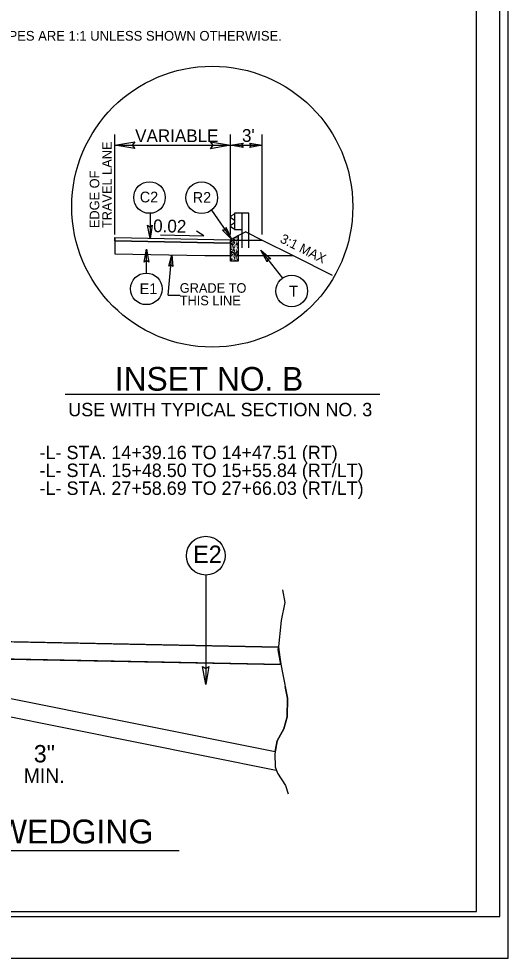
# Model space of a CAD drawing. Extents: x 573687 to 575553, y -54556 to -52223.
# Drawn here: x 575109 to 575371, y -53323 to -52818 of the extents above; entities that cross this region are included whole.
import ezdxf

# ---------------------------------------------------------------- set-up
doc = ezdxf.new("R2010")
doc.units = 0
for name, color, linetype in [('Default', 7, 'Continuous'), ('Old_Level_1', 7, 'Continuous'), ('Old_Level_11', 7, 'Continuous'), ('Old_Level_3', 7, 'Continuous'), ('Old_Level_7', 7, 'Continuous'), ('Prop Dimension', 7, 'Continuous'), ('Prop Dimension Text', 7, 'Continuous'), ('Sheet Cutting Line CELL', 7, 'Continuous'), ('Sheet Plot Border Inside CELL', 7, 'Continuous'), ('Sheet Plot Border Outside CELL', 7, 'Continuous'), ('Sheet Typical CELL', 7, 'Continuous'), ('Typical Arrow Superelevation CELL', 7, 'Continuous'), ('Typical Detail Wedge2 CELL', 7, 'Continuous'), ('Typical Guardrail CELL', 7, 'Continuous'), ('Typical ID Circle CELL', 7, 'Continuous'), ('Typical Terminator CELL', 7, 'Continuous'), ('Typical Text Label CELL', 7, 'Continuous')]:
    doc.layers.add(name, color=color, linetype=linetype)

msp = doc.modelspace()

# ---------------------------------------------------------------- linework, layer by layer
at = {"layer": 'Old_Level_1'}
for p, q in [((575160.28, -52934.26), (575160.28, -52880.59)), ((575222.36, -52934.26), (575222.36, -52880.59)), ((575239.42, -52934.26), (575239.42, -52880.59)), ((575160.28, -52886.27), (575222.36, -52886.27)), ((575222.36, -52886.27), (575239.42, -52886.27)), ((575160.24, -52937.56), (575222.32, -52938.8)), ((575160.28, -52935.73), (575222.36, -52936.97)), ((575160.28, -52935.73), (575160.28, -52944.5)), ((575222.36, -52937.19), (575239.42, -52937.19)), ((575230.67, -52932.82), (575226.3, -52935)), ((575230.67, -52932.82), (575239.42, -52937.19)), ((575239.42, -52937.19), (575255.96, -52945.46)), ((575226.43, -52940.08), (575226.43, -52944.11)), ((575160.28, -52944.5), (575208.54, -52945.46)), ((575208.54, -52945.46), (575222.36, -52945.46)), ((575226.43, -52945.46), (575235.57, -52945.46)), ((575235.57, -52945.46), (575255.96, -52945.46)), ((575255.96, -52945.46), (575276.92, -52955.94)), ((575133.52, -53019.85), (575302.48, -53019.85))]:
    msp.add_line(p, q, dxfattribs=at)
msp.add_lwpolyline([(575160.28, -52935.73), (575222.36, -52936.97), (575222.32, -52938.8), (575160.24, -52937.56)], close=True, dxfattribs=at)
msp.add_circle((575212.56, -52919.25), 75.42, dxfattribs=at)
at = {"layer": 'Old_Level_11'}
for q in [(575190.93, -52945.13), (575195.34, -52966.77)]:
    msp.add_line((575188.87, -52966.77), q, dxfattribs=at)
for points in [[(575170.94, -52888.11), (575160.28, -52886.27), (575171, -52884.38), (575169.64, -52886.27)], [(575211.7, -52884.44), (575222.36, -52886.27), (575211.64, -52888.17), (575213, -52886.27)], [(575189.27, -52951.17), (575190.93, -52945.13), (575191.43, -52951.38), (575190.42, -52950.52)]]:
    msp.add_lwpolyline(points, close=True, dxfattribs=at)
at = {"layer": 'Old_Level_3'}
for points in [[(575226.43, -52935.13), (575226.3, -52935), (575222.36, -52936.97)], [(575226.43, -52935.13), (575226.43, -52948.56), (575222.36, -52948.56), (575222.36, -52936.97)]]:
    msp.add_lwpolyline(points, dxfattribs=at)
for centre, start, end in [((575222.33, -52940.4), 309.7979, 50.2021), ((575226.46, -52946.02), 129.7979, 230.2021)]:
    msp.add_arc(centre, 0.0448, start, end, dxfattribs=at)
at = {"layer": 'Old_Level_7'}
msp.add_line((575225.84, -52943.73), (575225.66, -52944.13), dxfattribs=at)
for points in [[(575224.38, -52936.97), (575223.94, -52937.01), (575224.26, -52936.51), (575224.39, -52936.66)], [(575222.82, -52939.34), (575222.86, -52939.78), (575222.36, -52939.46), (575222.51, -52939.33)], [(575222.65, -52938.04), (575222.39, -52937.68), (575222.99, -52937.71), (575222.92, -52937.89)], [(575222.65, -52942.33), (575222.39, -52941.97), (575222.99, -52942), (575222.92, -52942.19)], [(575224.38, -52941.26), (575223.94, -52941.31), (575224.26, -52940.8), (575224.39, -52940.95)], [(575224.14, -52938.41), (575224.59, -52938.59), (575224.4, -52938.14), (575224.02, -52938.17)], [(575224.14, -52942.71), (575224.59, -52942.88), (575224.4, -52942.44), (575224.02, -52942.46)], [(575225.84, -52939.43), (575225.65, -52939.84), (575225.38, -52939.31), (575225.57, -52939.27)], [(575222.82, -52943.64), (575222.86, -52944.08), (575222.36, -52943.75), (575222.51, -52943.62)], [(575222.95, -52945.06), (575223.14, -52945.46), (575223.41, -52944.93), (575223.22, -52944.89)], [(575224.41, -52946.88), (575224.85, -52946.93), (575224.53, -52946.42), (575224.4, -52946.58)], [(575226.14, -52947.95), (575226.4, -52947.59), (575225.8, -52947.62), (575225.87, -52947.81)], [(575225.97, -52944.96), (575225.93, -52945.4), (575226.43, -52945.08), (575226.28, -52944.95)], [(575224.65, -52948.33), (575224.2, -52948.51), (575224.39, -52948.06), (575224.77, -52948.08)]]:
    msp.add_lwpolyline(points, close=True, dxfattribs=at)
for points in [[(575225.78, -52935.26), (575225.65, -52935.54), (575225.57, -52935.37)], [(575226.43, -52937.3), (575226.34, -52937.49), (575226.07, -52936.96), (575226.27, -52936.92), (575226.43, -52937.03)], [(575226.43, -52941.59), (575226.34, -52941.78), (575226.07, -52941.25), (575226.27, -52941.21), (575226.43, -52941.32)], [(575222.36, -52947.21), (575222.45, -52947.4), (575222.72, -52946.87), (575222.53, -52946.84), (575222.36, -52946.94)], [(575225.65, -52944.13), (575225.38, -52943.6), (575225.57, -52943.56), (575225.84, -52943.73)]]:
    msp.add_lwpolyline(points, dxfattribs=at)
for centre, radius in [((575223.15, -52937.02), 0.0448), ((575224.22, -52937.54), 0.0448), ((575224.51, -52936.09), 0.0448), ((575225.19, -52936.85), 0.0448), ((575225.37, -52936.07), 0.0448), ((575225.72, -52937.27), 0.0448), ((575225.97, -52935.8), 0.0475), ((575226.27, -52936.11), 0.0448), ((575222.56, -52938.35), 0.0448), ((575222.56, -52942.65), 0.0448), ((575222.71, -52940.87), 0.0448), ((575222.92, -52940.11), 0.0475), ((575222.93, -52938.93), 0.0487), ((575223.15, -52941.31), 0.0448), ((575223.35, -52940.38), 0.0448), ((575223.42, -52939.63), 0.0483), ((575223.52, -52939.01), 0.0448), ((575223.54, -52939.93), 0.0448), ((575223.54, -52940.29), 0.0448), ((575223.69, -52938.24), 0.0448), ((575223.69, -52942.53), 0.0448), ((575224.05, -52939.43), 0.0448), ((575224.14, -52939.91), 0.0301), ((575224.22, -52941.84), 0.0448), ((575224.41, -52939.05), 0.0448), ((575224.51, -52940.38), 0.0448), ((575224.7, -52940.11), 0.0448), ((575225.17, -52939.21), 0.0448), ((575225.19, -52941.14), 0.0448), ((575225.22, -52937.76), 0.0448), ((575225.22, -52942.05), 0.0448), ((575225.37, -52940.37), 0.0448), ((575225.5, -52938.34), 0.0448), ((575225.5, -52942.64), 0.0448), ((575225.72, -52941.56), 0.0448), ((575225.81, -52937.74), 0.0301), ((575225.81, -52942.04), 0.0301), ((575225.97, -52940.09), 0.0475), ((575225.98, -52938.91), 0.0487), ((575226.27, -52940.41), 0.0448), ((575226.38, -52937.94), 0.0448), ((575226.38, -52942.24), 0.0448), ((575222.52, -52946.03), 0.0448), ((575222.81, -52944.53), 0.0487), ((575222.82, -52945.72), 0.0475), ((575222.93, -52943.23), 0.0487), ((575222.98, -52947.66), 0.0301), ((575223.07, -52947.18), 0.0448), ((575223.42, -52943.92), 0.0483), ((575223.42, -52945.99), 0.0448), ((575223.52, -52943.31), 0.0448), ((575223.58, -52947.68), 0.0448), ((575223.6, -52946.76), 0.0448), ((575223.62, -52944.84), 0.0448), ((575223.88, -52944.24), 0.0448), ((575224.05, -52943.73), 0.0448), ((575224.09, -52945.73), 0.0448), ((575224.28, -52946), 0.0448), ((575224.38, -52944.67), 0.0448), ((575224.41, -52943.34), 0.0448), ((575224.57, -52947.46), 0.0448), ((575224.65, -52945.53), 0.0301), ((575224.74, -52945.05), 0.0448), ((575224.76, -52944.09), 0.0448), ((575225.17, -52943.51), 0.0448), ((575225.25, -52945.91), 0.0448), ((575225.25, -52945.55), 0.0448), ((575225.27, -52944.63), 0.0448), ((575225.37, -52945.25), 0.0483), ((575225.44, -52946), 0.0448), ((575225.64, -52946.93), 0.0448), ((575225.86, -52944.55), 0.0487), ((575225.87, -52945.73), 0.0475), ((575225.98, -52943.21), 0.0487), ((575226.08, -52946.5), 0.0448), ((575222.41, -52947.86), 0.0448), ((575223.29, -52948.26), 0.0448), ((575225.1, -52948.15), 0.0448), ((575226.23, -52948.27), 0.0448)]:
    msp.add_circle(centre, radius, dxfattribs=at)
for centre, radius, start, end in [((575224.7, -52935.81), 0.0448, 193.5972, 39.5125), ((575226.48, -52935.32), 0.0483, 157.2508, 202.7492), ((575226.48, -52939.61), 0.0483, 157.2508, 202.7492), ((575222.32, -52945.23), 0.0483, 337.2508, 22.7492), ((575226.48, -52943.91), 0.0483, 157.2508, 202.7492)]:
    msp.add_arc(centre, radius, start, end, dxfattribs=at)
at = {"layer": 'Prop Dimension'}
for p, q in [((575212.14, -52921.19), (575223, -52936.88)), ((575179.18, -52922.82), (575179.18, -52936.27)), ((575177.27, -52954.9), (575177.27, -52942.02)), ((575250.41, -52957.59), (575238.69, -52942.54))]:
    msp.add_line(p, q, dxfattribs=at)
msp.add_lwpolyline([(575015.22, -53151.04), (575015.22, -53165.42), (575015.22, -53165.42), (575030.42, -53168.44), (575035.69, -53160.96), (575035.82, -53160.77), (575050.38, -53161.07), (575085.1, -53161.76), (575085.1, -53161.76), (575085.1, -53161.76), (575249.4, -53165.04), (575247.96, -53157.18), (575248.1, -53155.87), (575248.08, -53155.69), (575015.24, -53151.04), (575015.22, -53151.04)], dxfattribs=at)
for centre in [(575178.87, -52914.34), (575206.93, -52914.48), (575177.14, -52963.37), (575255.24, -52964.57)]:
    msp.add_circle(centre, 8.49, dxfattribs=at)
at = {"layer": 'Prop Dimension Text'}
msp.add_line((574833.54, -53264.81), (575194.71, -53264.81), dxfattribs=at)
at = {"layer": 'Sheet Cutting Line CELL'}
msp.add_line((573687.43, -53322.67), (575371.43, -53322.67), dxfattribs=at)
at = {"layer": 'Sheet Plot Border Inside CELL'}
msp.add_lwpolyline([(575366.93, -52245.12), (573700.43, -52245.12), (573700.43, -53300.22), (575366.93, -53300.22)], close=True, dxfattribs=at)
at = {"layer": 'Sheet Plot Border Outside CELL'}
msp.add_lwpolyline([(575371.43, -52222.67), (573687.43, -52222.67), (573687.43, -53322.67), (575371.43, -53322.67)], close=True, dxfattribs=at)
at = {"layer": 'Sheet Typical CELL'}
msp.add_lwpolyline([(575354.43, -52247.67), (573854.43, -52247.67), (573854.43, -53297.67), (575354.43, -53297.67)], close=True, dxfattribs=at)
at = {"layer": 'Typical Arrow Superelevation CELL'}
for p, q in [((575208.05, -52934.97), (575204.16, -52932.34)), ((575184.83, -52934.3), (575208.05, -52934.97))]:
    msp.add_line(p, q, dxfattribs=at)
at = {"layer": 'Typical Detail Wedge2 CELL'}
for p, q in [((575015.22, -53151.04), (575248.08, -53155.69)), ((575015.24, -53151.04), (575248.08, -53155.69)), ((575248.08, -53155.69), (575249.41, -53165.05)), ((575035.82, -53160.77), (575249.41, -53165.05)), ((575249.41, -53165.05), (575035.82, -53160.77)), ((575030.42, -53168.44), (575246.33, -53211.66)), ((575015.31, -53175.32), (575246.94, -53221.65))]:
    msp.add_line(p, q, dxfattribs=at)
for points in [[(575250.23, -53124.96), (575251.47, -53131.78), (575249.62, -53141.48), (575247.96, -53157.18), (575250.23, -53169.57), (575252.92, -53183), (575252.71, -53193.12), (575251.05, -53199.52), (575247.34, -53205.93), (575246.11, -53212.95), (575246.3, -53219.97), (575247.54, -53223.28), (575251.88, -53229.89), (575253.32, -53234.43)], [(575246.33, -53211.65), (575247.34, -53205.93), (575251.05, -53199.52), (575252.71, -53193.12), (575252.92, -53183), (575251.67, -53176.77)]]:
    msp.add_lwpolyline(points, dxfattribs=at)
at = {"layer": 'Typical Guardrail CELL'}
for p, q in [((575222.69, -52924.25), (575223.89, -52923.41)), ((575222.69, -52925.23), (575224.29, -52926.34)), ((575223.99, -52923.37), (575224.54, -52923.27)), ((575232.16, -52922.71), (575224.54, -52922.71)), ((575224.54, -52922.71), (575224.54, -52931.6)), ((575228.35, -52922.74), (575228.35, -52941.3)), ((575232.16, -52941.3), (575232.16, -52922.74)), ((575222.69, -52929.09), (575224.29, -52927.97)), ((575222.69, -52930.07), (575223.89, -52930.92)), ((575224.01, -52930.96), (575224.54, -52931.05)), ((575224.54, -52931.6), (575228.35, -52931.6))]:
    msp.add_line(p, q, dxfattribs=at)
for points in [[(575229.12, -52887.46), (575222.36, -52886.27), (575229.12, -52885.09), (575228.29, -52886.27)], [(575232.66, -52885.09), (575239.42, -52886.27), (575232.66, -52887.46), (575233.49, -52886.27)]]:
    msp.add_lwpolyline(points, close=True, dxfattribs=at)
for centre, radius, start, end in [((575223.03, -52924.74), 0.595, 125.0033, 234.9967), ((575224.03, -52923.6), 0.239, 100.0493, 125.0389), ((575223.94, -52926.83), 0.595, 0, 54.9829), ((575223.94, -52927.49), 0.595, 305.0171, 0), ((575223.03, -52929.58), 0.595, 125.0033, 234.9967), ((575224.03, -52930.72), 0.239, 234.9611, 266.1456)]:
    msp.add_arc(centre, radius, start, end, dxfattribs=at)
at = {"layer": 'Typical ID Circle CELL'}
msp.add_line((575209.09, -53117), (575209.09, -53175.7), dxfattribs=at)
msp.add_circle((575209.09, -53106.6), 10.4, dxfattribs=at)
at = {"layer": 'Typical Terminator CELL'}
for points in [[(575180.33, -52929.27), (575179.18, -52936.27), (575177.88, -52929.25), (575179.13, -52930.14)], [(575218.03, -52931.81), (575223, -52936.88), (575220.02, -52930.39), (575219.5, -52931.83)], [(575176.07, -52949.01), (575177.27, -52942.02), (575178.51, -52949.05), (575177.27, -52948.15)], [(575242.03, -52948.79), (575238.69, -52942.54), (575243.99, -52947.32), (575242.46, -52947.38)], [(575210.75, -53166.07), (575209.09, -53175.7), (575207.38, -53166.01), (575209.09, -53167.24)]]:
    msp.add_lwpolyline(points, close=True, dxfattribs=at)

# ---------------------------------------------------------------- texts
at = {"layer": 'Default'}
for s, height, p in [('NOTE: PAVEMENT EDGE SLOPES ARE 1:1 UNLESS SHOWN OTHERWISE.', 5.224, (575003.82, -52830.16)), ('-L- STA. 14+39.16 TO 14+47.51 (RT)', 7.2, (575119.89, -53054.78)), ('-L- STA. 15+48.50 TO 15+55.84 (RT/LT)', 7.2, (575119.89, -53064.38)), ('-L- STA. 27+58.69 TO 27+66.03 (RT/LT)', 7.2, (575119.89, -53073.98))]:
    msp.add_text(s, height=height, dxfattribs=at).set_placement(p)
at = {"layer": 'Old_Level_1'}
for s, p in [('VARIABLE', (575171.17, -52884.63)), ("3'", (575228.52, -52884.46))]:
    msp.add_text(s, height=6.835, dxfattribs=at).set_placement(p)
msp.add_text('3:1 MAX', height=5.126, rotation=333.4349, dxfattribs=at).set_placement((575248.5, -52938.16))
at = {"layer": 'Prop Dimension Text'}
for s, height, p in [('C2', 5.778, (575173.65, -52916.97)), ('R2', 5.778, (575202.07, -52917.19)), ('E1', 5.778, (575173.58, -52966.19)), ('T', 5.78, (575253.83, -52967.52))]:
    msp.add_text(s, height=height, dxfattribs=at).set_placement(p)
msp.add_text('E2', height=9.35, rotation=0.0001, dxfattribs=at).set_placement((575202.34, -53110.53))
at = {"layer": 'Typical Detail Wedge2 CELL'}
for s, height, p in [('3"', 9.309, (575116.77, -53217.55)), ('MIN.', 7.779, (575111.36, -53228.54))]:
    msp.add_text(s, height=height, rotation=0.0001, dxfattribs=at).set_placement(p)
at = {"layer": 'Typical Text Label CELL'}
for s, height, rotation, p in [('TRAVEL LANE', 5.1263, 90, (575158.64, -52930.77)), ('EDGE OF', 5.126, 90, (575151.92, -52930.77)), (' 0.02', 6.835, 358.8083, (575178.24, -52932.85)), ('INSET NO. B', 12.7159, 360, (575160.29, -53018.03)), ('USE WITH TYPICAL SECTION NO. 3', 7.2, 360, (575135.26, -53031.77)), ('DETAIL SHOWING METHOD OF WEDGING', 12.8401, 0.0001, (574835.6, -53261.09))]:
    msp.add_text(s, height=height, rotation=rotation, dxfattribs=at).set_placement(p)
for s, p in [('GRADE TO', (575195.11, -52965.46)), ('THIS LINE', (575195.11, -52972.18))]:
    msp.add_text(s, height=5.126, dxfattribs=at).set_placement(p)

doc.saveas('drawing.dxf')
